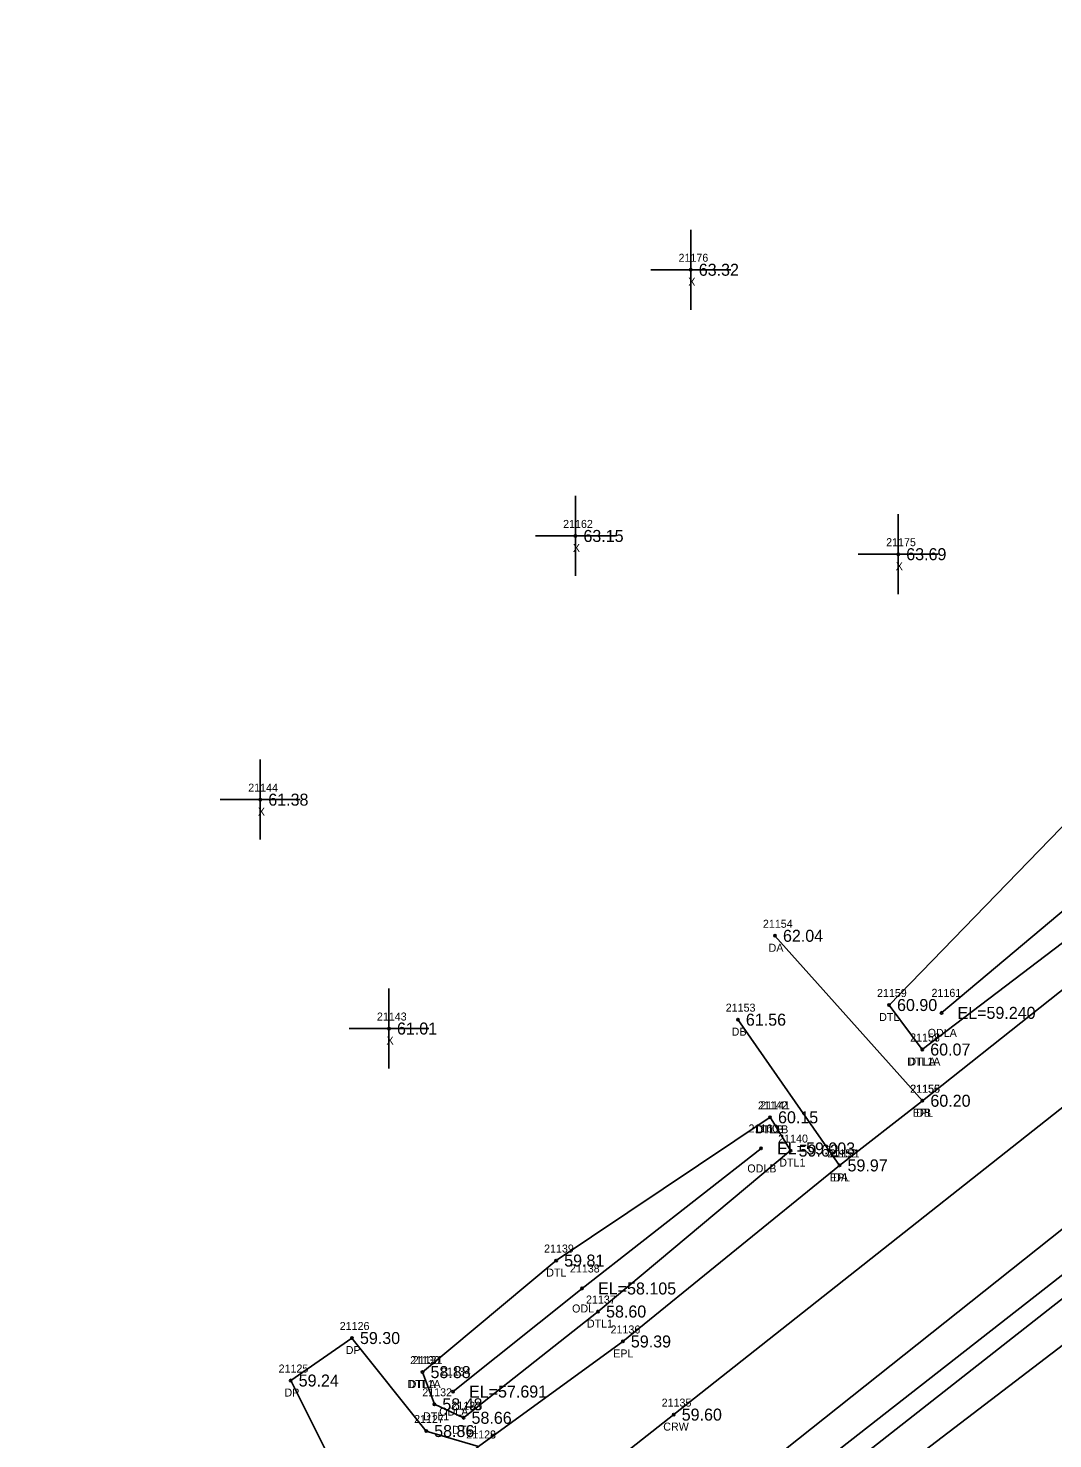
# Model space of a CAD drawing. Extents: x 2420351 to 2422725, y 845330 to 846558.
# Drawn here: x 2422361.1 to 2422489.2, y 846312.6 to 846488.9 of the extents above; entities that cross this region are included whole.
import ezdxf

# ---------------------------------------------------------------- set-up
doc = ezdxf.new("R2010")
doc.units = 0
for name, color, linetype in [('RD_DTM_BkLn1', 7, 'Continuous'), ('RD_EX_Driveway', 7, 'Continuous'), ('RD_EX_Driveway_txCode', 7, 'Continuous'), ('RD_EX_H2O', 7, 'Continuous'), ('RD_EX_H2O_txCode', 7, 'Continuous'), ('RD_EX_Misc', 7, 'Continuous'), ('RD_EX_Misc_txCode', 7, 'Continuous'), ('RD_EX_Road', 7, 'Continuous'), ('RD_EX_Road_txCode', 7, 'Continuous'), ('RD_EX_TX_Driveway_ELEV', 7, 'Continuous'), ('RD_EX_TX_H2O_ELEV', 7, 'Continuous'), ('RD_EX_TX_Misc_ELEV', 7, 'Continuous'), ('RD_EX_TX_Road_ELEV', 7, 'Continuous'), ('RD_HC_Survey_ELEV', 7, 'Continuous'), ('RD_HC_Survey_txCode', 7, 'Continuous'), ('RD_SMD_Locator', 7, 'Continuous')]:
    doc.layers.add(name, color=color, linetype=linetype)

msp = doc.modelspace()

# ---------------------------------------------------------------- linework, layer by layer
at = {"layer": 'RD_DTM_BkLn1'}
msp.add_lwpolyline([(2421809.69, 845832.82), (2421858.88, 845863.61), (2421946.63, 845925.83), (2421988.11, 845958.04), (2422060.85, 846015.47), (2422145.87, 846082.37), (2422217.73, 846139.26), (2422291.07, 846197.06), (2422441.76, 846315.63), (2422509.48, 846369.12), (2422585.38, 846428.46), (2422650.19, 846479.15)], dxfattribs=at)
at = {"layer": 'RD_EX_Driveway'}
for p, q in [((2422454.42, 846375.46), (2422472.85, 846354.85)), ((2422462.49, 846346.77), (2422449.78, 846364.98))]:
    msp.add_line(p, q, dxfattribs=at)
msp.add_lwpolyline([(2422400.82, 846297.88), (2422400.34, 846306.99), (2422393.87, 846319.89), (2422401.53, 846325.2), (2422410.81, 846313.58), (2422417.34, 846311.65)], dxfattribs=at)
at = {"layer": 'RD_EX_H2O'}
for points in [[(2422472.83, 846361.25), (2422468.68, 846366.81), (2422492.83, 846391.64), (2422569.21, 846449.39), (2422595.74, 846472)], [(2422472.83, 846361.25), (2422499.74, 846381.72), (2422575.73, 846440.62), (2422602, 846462.6), (2422600.58, 846468.4), (2422595.74, 846472)], [(2422383.12, 846248.84), (2422451.79, 846302.96), (2422519.84, 846356.14), (2422594.22, 846416.85), (2422660.96, 846466.59)], [(2422386.28, 846248.04), (2422453.27, 846301.01), (2422520.96, 846354.14), (2422596.31, 846414.61), (2422662.29, 846464.81)], [(2422475.24, 846365.83), (2422497.83, 846384.79), (2422574.42, 846442.29), (2422598.85, 846463.65)], [(2422383.12, 846248.84), (2422386.53, 846244.46), (2422456.45, 846298.4), (2422524.56, 846350.4), (2422601.29, 846410.12), (2422664.82, 846461.69)], [(2422410.35, 846320.94), (2422427.06, 846334.88), (2422453.8, 846352.78)], [(2422410.35, 846320.94), (2422411.83, 846316.92), (2422415.48, 846315.23), (2422432.3, 846328.51), (2422456.37, 846348.62), (2422453.8, 846352.78)], [(2422414.17, 846318.51), (2422430.3, 846331.39), (2422452.68, 846348.89)]]:
    msp.add_lwpolyline(points, dxfattribs=at)
at = {"layer": 'RD_EX_Misc'}
for p, q in [((2422443.89, 846453.68), (2422443.89, 846463.68)), ((2422438.89, 846458.68), (2422448.89, 846458.68)), ((2422429.47, 846420.42), (2422429.47, 846430.42)), ((2422469.83, 846418.14), (2422469.83, 846428.14)), ((2422424.47, 846425.42), (2422434.47, 846425.42)), ((2422464.83, 846423.14), (2422474.83, 846423.14)), ((2422390.07, 846387.47), (2422390.07, 846397.47)), ((2422385.07, 846392.47), (2422395.07, 846392.47)), ((2422406.16, 846358.87), (2422406.16, 846368.87)), ((2422401.16, 846363.87), (2422411.16, 846363.87))]:
    msp.add_line(p, q, dxfattribs=at)
at = {"layer": 'RD_EX_Road'}
for points in [[(2421810.77, 845819.82), (2421809.69, 845832.82), (2421803.88, 845842.86), (2421852.96, 845873.69), (2421939.48, 845935.12), (2421980.78, 845967.01), (2422140.12, 846092.81), (2422210.03, 846148.43), (2422282.88, 846205.21), (2422291.79, 846212.09), (2422354.49, 846261.98), (2422400.82, 846297.88), (2422417.34, 846311.65), (2422435.4, 846324.77), (2422462.49, 846346.77), (2422472.85, 846354.85), (2422502.3, 846378.16), (2422578.05, 846437.54), (2422605.64, 846459.09), (2422626.64, 846476.17), (2422642.61, 846488.86)], [(2421810.77, 845819.82), (2421865.31, 845853.52), (2421953.26, 845916.07), (2421995.06, 845948.03), (2422068.36, 846005.98), (2422153.46, 846073.36), (2422229.55, 846134.03), (2422245.4, 846145.63), (2422297.08, 846186.88), (2422369.77, 846243.69), (2422382.04, 846253.08), (2422449.02, 846305.97), (2422517.14, 846360.1), (2422592.58, 846419.1), (2422657.51, 846470.1)]]:
    msp.add_lwpolyline(points, dxfattribs=at)
at = {"layer": 'RD_SMD_Locator'}
for centre in [(2422443.89, 846458.68), (2422429.47, 846425.42), (2422469.83, 846423.14), (2422390.07, 846392.47), (2422454.42, 846375.46), (2422468.68, 846366.81), (2422449.78, 846364.98), (2422475.24, 846365.83), (2422406.16, 846363.87), (2422472.83, 846361.25), (2422472.83, 846361.25), (2422472.85, 846354.85), (2422472.85, 846354.85), (2422453.8, 846352.78), (2422453.8, 846352.78), (2422452.68, 846348.89), (2422456.37, 846348.62), (2422462.49, 846346.77), (2422462.49, 846346.77), (2422427.06, 846334.88), (2422430.3, 846331.39), (2422432.3, 846328.51), (2422401.53, 846325.2), (2422435.4, 846324.77), (2422410.35, 846320.94), (2422410.35, 846320.94), (2422393.87, 846319.89), (2422414.17, 846318.51), (2422411.83, 846316.92), (2422415.48, 846315.23), (2422441.76, 846315.63), (2422410.81, 846313.58)]:
    msp.add_circle(centre, 0.15, dxfattribs=at)

# ---------------------------------------------------------------- texts
at = {"layer": 'RD_EX_Driveway_txCode'}
for s, p in [('21154', (2422452.91, 846376.46)), ('DA', (2422453.62, 846373.46)), ('21153', (2422448.26, 846365.98)), ('DB', (2422449, 846362.98)), ('21155', (2422471.34, 846355.85)), ('DB', (2422472.07, 846352.85)), ('21152', (2422460.98, 846347.77)), ('DA', (2422461.7, 846344.77)), ('21126', (2422400, 846326.2)), ('DP', (2422400.75, 846323.2)), ('21125', (2422392.36, 846320.89)), ('DP', (2422393.09, 846317.89)), ('21127', (2422409.3, 846314.58)), ('21128', (2422415.82, 846312.65))]:
    msp.add_text(s, height=1, dxfattribs=at).set_placement(p)
at = {"layer": 'RD_EX_H2O_txCode'}
for s, p in [('21159', (2422467.17, 846367.81)), ('21161', (2422473.99, 846367.83)), ('DTL', (2422467.44, 846364.81)), ('21157', (2422471.32, 846362.25)), ('21158', (2422471.32, 846362.25)), ('ODLA', (2422473.51, 846362.83)), ('DTL1A', (2422470.93, 846359.25)), ('DTLA', (2422471.1, 846359.25)), ('21142', (2422452.29, 846353.78)), ('21141', (2422452.57, 846353.78)), ('21160', (2422451.11, 846350.89)), ('DTL1B', (2422451.92, 846350.78)), ('DTLB', (2422452.08, 846350.78)), ('21140', (2422454.82, 846349.62)), ('ODLB', (2422450.96, 846345.89)), ('DTL1', (2422454.96, 846346.62)), ('21139', (2422425.55, 846335.88)), ('21138', (2422428.78, 846333.39)), ('DTL', (2422425.82, 846332.88)), ('ODL', (2422429.05, 846328.39)), ('21137', (2422430.79, 846329.51)), ('DTL1', (2422430.9, 846326.51)), ('21130', (2422408.8, 846321.94)), ('21131', (2422409.13, 846321.94)), ('21134', (2422412.66, 846320.51)), ('DTL1A', (2422408.46, 846318.94)), ('DTLA', (2422408.62, 846318.94)), ('21132', (2422410.32, 846317.92)), ('21133', (2422413.96, 846316.23)), ('DTL1', (2422410.42, 846314.92)), ('ODLA', (2422412.44, 846315.51)), ('DTL1', (2422414.07, 846313.23))]:
    msp.add_text(s, height=1, dxfattribs=at).set_placement(p)
at = {"layer": 'RD_EX_Misc_txCode'}
for s, p in [('21176', (2422442.36, 846459.68)), ('X', (2422443.58, 846456.68)), ('21162', (2422427.93, 846426.42)), ('X', (2422429.15, 846423.42)), ('21175', (2422468.32, 846424.14)), ('X', (2422469.52, 846421.14)), ('21144', (2422388.56, 846393.47)), ('X', (2422389.76, 846390.47)), ('21143', (2422404.65, 846364.87)), ('X', (2422405.85, 846361.87))]:
    msp.add_text(s, height=1, dxfattribs=at).set_placement(p)
at = {"layer": 'RD_EX_Road_txCode'}
for s, p in [('21156', (2422471.31, 846355.85)), ('EPL', (2422471.64, 846352.85)), ('21151', (2422461.27, 846347.77)), ('EPL', (2422461.29, 846344.77)), ('21136', (2422433.86, 846325.77)), ('EPL', (2422434.19, 846322.77)), ('21129', (2422415.82, 846312.65))]:
    msp.add_text(s, height=1, dxfattribs=at).set_placement(p)
at = {"layer": 'RD_EX_TX_Driveway_ELEV'}
for s, p in [('62.04', (2422455.42, 846374.71)), ('61.56', (2422450.78, 846364.23)), ('60.20', (2422473.85, 846354.1)), ('59.97', (2422463.49, 846346.02)), ('59.30', (2422402.53, 846324.45)), ('59.24', (2422394.87, 846319.14)), ('58.86', (2422411.81, 846312.83))]:
    msp.add_text(s, height=1.5, dxfattribs=at).set_placement(p)
at = {"layer": 'RD_EX_TX_H2O_ELEV'}
for s, p in [('60.90', (2422469.68, 846366.06)), ('EL=59.240', (2422477.24, 846365.08)), ('60.07', (2422473.83, 846360.5)), ('60.07', (2422473.83, 846360.5)), ('60.15', (2422454.8, 846352.03)), ('60.15', (2422454.8, 846352.03)), ('EL=59.003', (2422454.68, 846348.14)), ('59.62', (2422457.37, 846347.87)), ('59.81', (2422428.06, 846334.13)), ('EL=58.105', (2422432.3, 846330.64)), ('58.60', (2422433.3, 846327.76)), ('58.88', (2422411.35, 846320.19)), ('58.88', (2422411.35, 846320.19)), ('EL=57.691', (2422416.17, 846317.76)), ('58.48', (2422412.83, 846316.17)), ('58.66', (2422416.48, 846314.48))]:
    msp.add_text(s, height=1.5, dxfattribs=at).set_placement(p)
at = {"layer": 'RD_EX_TX_Misc_ELEV'}
for s, p in [('63.32', (2422444.89, 846457.93)), ('63.15', (2422430.47, 846424.67)), ('63.69', (2422470.83, 846422.39)), ('61.38', (2422391.07, 846391.72)), ('61.01', (2422407.16, 846363.12))]:
    msp.add_text(s, height=1.5, dxfattribs=at).set_placement(p)
at = {"layer": 'RD_EX_TX_Road_ELEV'}
for s, p in [('60.20', (2422473.85, 846354.1)), ('59.97', (2422463.49, 846346.02)), ('59.39', (2422436.4, 846324.02))]:
    msp.add_text(s, height=1.5, dxfattribs=at).set_placement(p)
at = {"layer": 'RD_HC_Survey_ELEV'}
msp.add_text('59.60', height=1.5, dxfattribs=at).set_placement((2422442.76, 846314.88))
at = {"layer": 'RD_HC_Survey_txCode'}
for s, p in [('21135', (2422440.25, 846316.63)), ('CRW', (2422440.45, 846313.63))]:
    msp.add_text(s, height=1, dxfattribs=at).set_placement(p)

doc.saveas('drawing.dxf')
